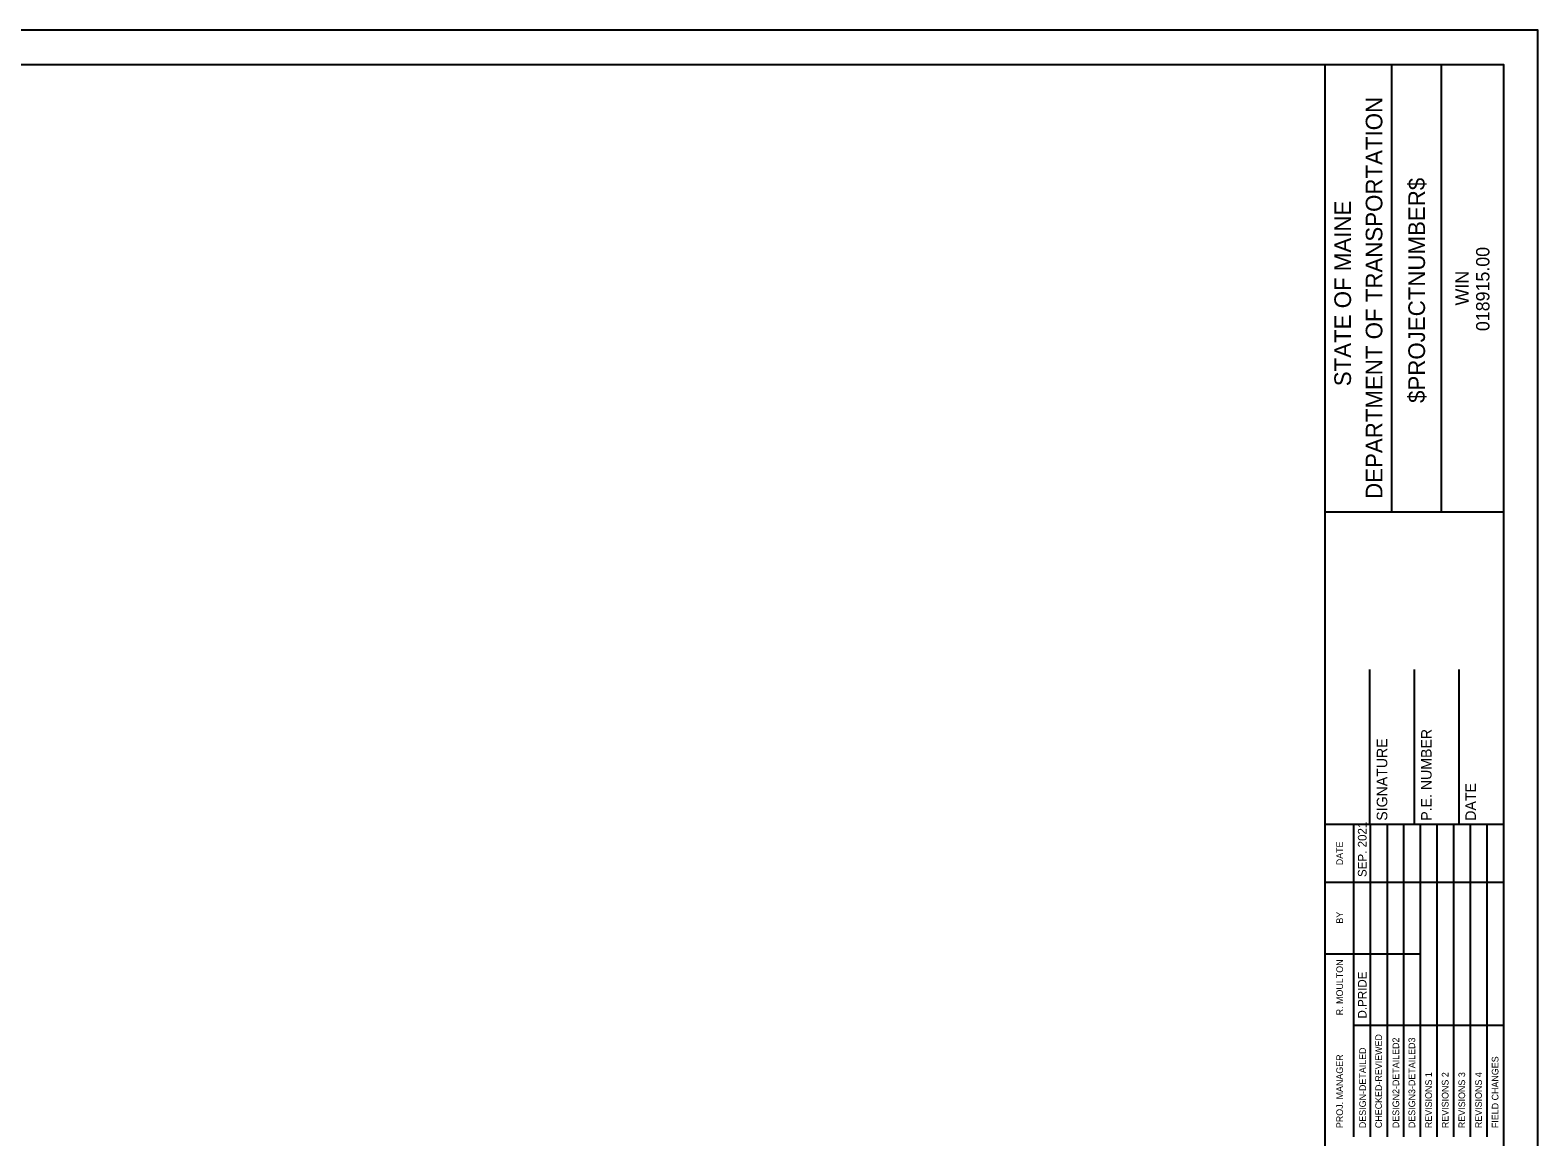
# Model space of a CAD drawing. Extents: x 1825540 to 1825883, y 442591 to 442811.
# Drawn here: x 1825711.4 to 1825880.1, y 442686.7 to 442810.5 of the extents above; entities that cross this region are included whole.
import ezdxf

# ---------------------------------------------------------------- set-up
doc = ezdxf.new("R2010")
doc.units = 0
doc.layers.add('BORDER', color=7, linetype='Continuous')
doc.layers.add('PLOT BOUNDARY', color=7, linetype='Continuous')

msp = doc.modelspace()

# ---------------------------------------------------------------- linework, layer by layer
at = {"layer": 'BORDER'}
for p, q in [((1825856.27, 442596.67), (1825856.27, 442806.67)), ((1825863.73, 442756.66), (1825863.73, 442806.66)), ((1825869.32, 442756.66), (1825869.32, 442806.66)), ((1825856.28, 442756.65), (1825876.27, 442756.65)), ((1825861.27, 442721.67), (1825861.27, 442738.97)), ((1825866.27, 442721.67), (1825866.27, 442738.97)), ((1825871.27, 442721.67), (1825871.27, 442738.97)), ((1825856.27, 442721.67), (1825876.27, 442721.67))]:
    msp.add_line(p, q, dxfattribs=at)
msp.add_lwpolyline([(1825556.27, 442596.67), (1825876.27, 442596.67), (1825876.27, 442806.67), (1825556.27, 442806.67)], close=True, dxfattribs=at)
for points in [[(1825859.5, 442715.17), (1825859.5, 442721.67)], [(1825861.37, 442686.68), (1825861.37, 442721.67)], [(1825863.23, 442721.67), (1825863.23, 442686.68)], [(1825865.1, 442686.68), (1825865.1, 442721.67)], [(1825866.96, 442686.68), (1825866.96, 442721.67)], [(1825868.82, 442686.68), (1825868.82, 442721.67)], [(1825870.69, 442686.68), (1825870.69, 442721.67)], [(1825872.55, 442686.68), (1825872.55, 442721.67)], [(1825874.41, 442686.68), (1825874.41, 442721.67)], [(1825859.51, 442686.68), (1825859.51, 442720.26)], [(1825856.27, 442715.17), (1825876.27, 442715.17)], [(1825856.27, 442707.17), (1825859.51, 442707.17)], [(1825859.5, 442707.17), (1825866.96, 442707.17)], [(1825859.5, 442699.17), (1825876.27, 442699.17)]]:
    msp.add_lwpolyline(points, dxfattribs=at)
at = {"layer": 'PLOT BOUNDARY'}
msp.add_lwpolyline([(1825540.09, 442590.55), (1825880.09, 442590.55), (1825880.09, 442810.55), (1825540.09, 442810.55)], close=True, dxfattribs=at)
msp.add_lwpolyline([(1825540.09, 442590.55), (1825880.09, 442590.55), (1825880.09, 442810.55), (1825540.09, 442810.55)], close=True, dxfattribs=at)

# ---------------------------------------------------------------- texts
at = {"layer": 'BORDER'}
for s, height, p in [('DEPARTMENT OF TRANSPORTATION', 1.8635, (1825862.69, 442758.08)), ('$PROJECTNUMBER$', 1.8635, (1825867.46, 442768.82)), ('STATE OF MAINE', 1.8635, (1825859.18, 442770.69)), ('018915.00', 1.491, (1825874.67, 442776.86)), ('WIN', 1.491, (1825872.35, 442779.73)), ('SIGNATURE', 1.181, (1825863.24, 442722.06)), ('P.E. NUMBER', 1.1811, (1825868.2, 442722.06)), ('DATE', 1.181, (1825873.16, 442722.06)), ('SEP. 2021', 0.969, (1825860.92, 442715.76)), ('DATE', 0.743, (1825858.28, 442717.08)), ('BY', 0.743, (1825858.28, 442710.54)), ('R. MOULTON', 0.745, (1825858.28, 442700.28)), ('D.PRIDE', 0.969, (1825860.92, 442699.92)), ('CHECKED-REVIEWED', 0.7455, (1825862.64, 442687.65)), ('DESIGN2-DETAILED2', 0.7455, (1825864.57, 442687.65)), ('DESIGN3-DETAILED3', 0.7455, (1825866.36, 442687.65)), ('PROJ. MANAGER', 0.7455, (1825858.28, 442687.65)), ('DESIGN-DETAILED', 0.7455, (1825860.85, 442687.65)), ('FIELD CHANGES', 0.7455, (1825875.68, 442687.65)), ('REVISIONS 1', 0.7455, (1825868.23, 442687.65)), ('REVISIONS 2', 0.7455, (1825870.09, 442687.65)), ('REVISIONS 3', 0.7455, (1825871.95, 442687.65)), ('REVISIONS 4', 0.7455, (1825873.82, 442687.65))]:
    msp.add_text(s, height=height, rotation=90, dxfattribs=at).set_placement(p)

doc.saveas('drawing.dxf')
